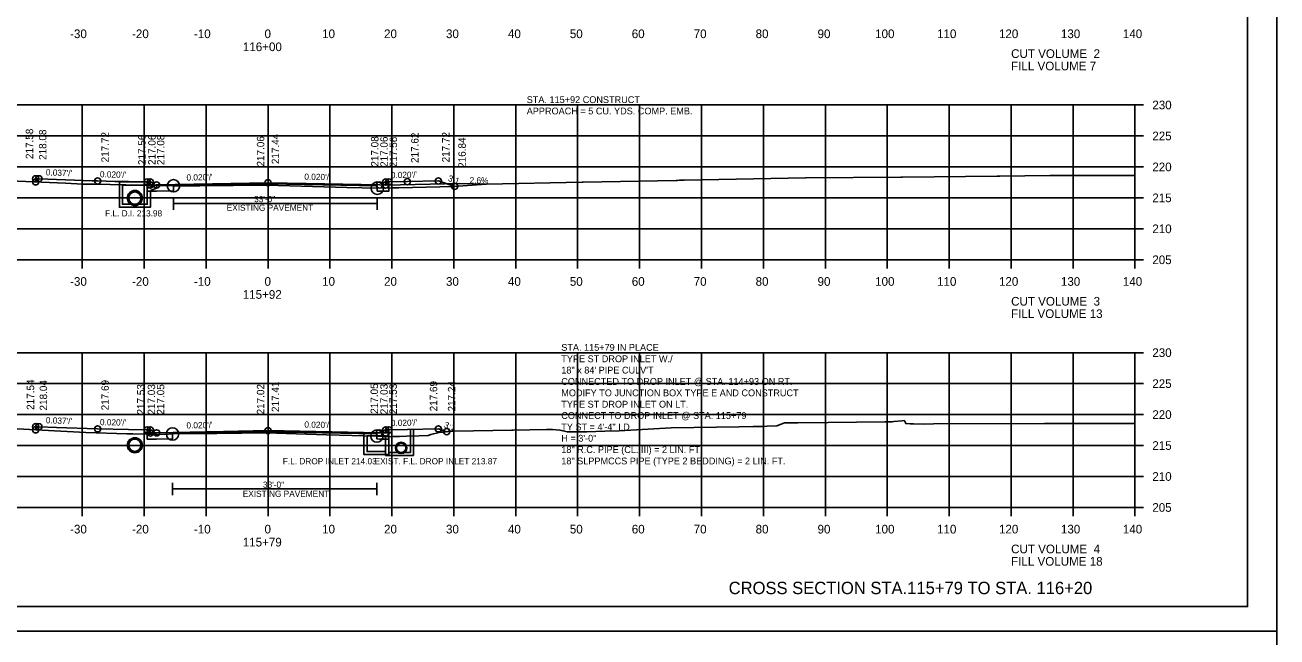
# Model space of a CAD drawing. Extents: x 1368968 to 1369915, y 377395 to 380381.
# Drawn here: x 1369712.5 to 1369914.7, y 378887.1 to 378986 of the extents above; entities that cross this region are included whole.
import ezdxf

# ---------------------------------------------------------------- set-up
doc = ezdxf.new("R2010")
doc.units = 0
for name, color, linetype in [('Default', 7, 'Continuous'), ('S_BORDER_NO_PLOT', 7, 'Continuous'), ('S_BREAKLINE_ANNOT', 7, 'Continuous'), ('S_BRIDGE', 7, 'Continuous'), ('S_BRIDGE_ANNOT', 7, 'Continuous'), ('S_CONTOUR_MINOR', 7, 'Continuous'), ('S_CROSS_DRAIN', 7, 'Continuous'), ('S_CTL_TABLE', 7, 'Continuous'), ('S_CURB_ANNOT', 7, 'Continuous'), ('S_DITCHLINE_ANNOT', 7, 'Continuous'), ('S_DROP_INLET', 7, 'Continuous'), ('S_EXIST_ROW_ANNOT', 7, 'Continuous'), ('S_EXISTING_ALIGNMENT_ANNOT', 7, 'Continuous'), ('S_FENCE', 7, 'Continuous')]:
    doc.layers.add(name, color=color, linetype=linetype)

msp = doc.modelspace()

# ---------------------------------------------------------------- linework, layer by layer
at = {"layer": 'Default'}
for p, q in [((1369736.52, 378960.01), (1369736.52, 378959.18)), ((1369774.78, 378919.56), (1369774.78, 378920.64)), ((1369775.28, 378919.58), (1369775.28, 378920.65)), ((1369736.37, 378919.97), (1369736.37, 378919.14)), ((1369770.78, 378916.41), (1369770.78, 378919.47)), ((1369771.28, 378916.91), (1369771.28, 378919.48)), ((1369774.78, 378916.91), (1369774.78, 378919.56)), ((1369775.28, 378916.41), (1369775.28, 378919.58)), ((1369771.28, 378916.91), (1369774.78, 378916.91)), ((1369770.78, 378916.41), (1369775.28, 378916.41))]:
    msp.add_line(p, q, dxfattribs=at)
at = {"layer": 'S_BORDER_NO_PLOT'}
for points in [[(1369732.27, 378960.61), (1369732.28, 378959.1), (1369733.78, 378959.13), (1369736.52, 378959.18), (1369736.52, 378960.01), (1369751.78, 378960.32), (1369769.43, 378959.96), (1369769.43, 378959.13), (1369769.78, 378959.13), (1369771.28, 378959.1), (1369771.29, 378960.61)], [(1369732.27, 378920.57), (1369732.28, 378919.06), (1369733.78, 378919.09), (1369736.37, 378919.14), (1369736.37, 378919.97), (1369751.78, 378920.28), (1369769.36, 378919.93), (1369769.36, 378919.1), (1369769.78, 378919.09), (1369771.28, 378919.06), (1369771.29, 378920.57)]]:
    msp.add_lwpolyline(points, dxfattribs=at)
at = {"layer": 'S_BREAKLINE_ANNOT'}
for p, q in [((1369891.78, 378948.04), (1369891.78, 378973.04)), ((1369893.18, 378973.04), (1369891.78, 378973.04)), ((1369893.18, 378968.04), (1369891.78, 378968.04)), ((1369893.18, 378963.04), (1369891.78, 378963.04)), ((1369893.18, 378958.04), (1369891.78, 378958.04)), ((1369893.18, 378953.04), (1369891.78, 378953.04)), ((1369611.78, 378948.04), (1369891.78, 378948.04)), ((1369721.78, 378946.64), (1369721.78, 378948.04)), ((1369731.78, 378946.64), (1369731.78, 378948.04)), ((1369741.78, 378946.64), (1369741.78, 378948.04)), ((1369751.78, 378946.64), (1369751.78, 378948.04)), ((1369761.78, 378946.64), (1369761.78, 378948.04)), ((1369771.78, 378946.64), (1369771.78, 378948.04)), ((1369781.78, 378946.64), (1369781.78, 378948.04)), ((1369791.78, 378946.64), (1369791.78, 378948.04)), ((1369801.78, 378946.64), (1369801.78, 378948.04)), ((1369811.78, 378946.64), (1369811.78, 378948.04)), ((1369821.78, 378946.64), (1369821.78, 378948.04)), ((1369831.78, 378946.64), (1369831.78, 378948.04)), ((1369841.78, 378946.64), (1369841.78, 378948.04)), ((1369851.78, 378946.64), (1369851.78, 378948.04)), ((1369861.78, 378946.64), (1369861.78, 378948.04)), ((1369871.78, 378946.64), (1369871.78, 378948.04)), ((1369881.78, 378946.64), (1369881.78, 378948.04)), ((1369891.78, 378946.64), (1369891.78, 378948.04)), ((1369893.18, 378948.04), (1369891.78, 378948.04)), ((1369891.78, 378908.04), (1369891.78, 378933.04)), ((1369893.18, 378933.04), (1369891.78, 378933.04)), ((1369893.18, 378928.04), (1369891.78, 378928.04)), ((1369893.18, 378923.04), (1369891.78, 378923.04)), ((1369893.18, 378918.04), (1369891.78, 378918.04)), ((1369893.18, 378913.04), (1369891.78, 378913.04)), ((1369611.78, 378908.04), (1369891.78, 378908.04)), ((1369721.78, 378906.64), (1369721.78, 378908.04)), ((1369731.78, 378906.64), (1369731.78, 378908.04)), ((1369741.78, 378906.64), (1369741.78, 378908.04)), ((1369751.78, 378906.64), (1369751.78, 378908.04)), ((1369761.78, 378906.64), (1369761.78, 378908.04)), ((1369771.78, 378906.64), (1369771.78, 378908.04)), ((1369781.78, 378906.64), (1369781.78, 378908.04)), ((1369791.78, 378906.64), (1369791.78, 378908.04)), ((1369801.78, 378906.64), (1369801.78, 378908.04)), ((1369811.78, 378906.64), (1369811.78, 378908.04)), ((1369821.78, 378906.64), (1369821.78, 378908.04)), ((1369831.78, 378906.64), (1369831.78, 378908.04)), ((1369841.78, 378906.64), (1369841.78, 378908.04)), ((1369851.78, 378906.64), (1369851.78, 378908.04)), ((1369861.78, 378906.64), (1369861.78, 378908.04)), ((1369871.78, 378906.64), (1369871.78, 378908.04)), ((1369881.78, 378906.64), (1369881.78, 378908.04)), ((1369891.78, 378906.64), (1369891.78, 378908.04)), ((1369893.18, 378908.04), (1369891.78, 378908.04))]:
    msp.add_line(p, q, dxfattribs=at)
at = {"layer": 'S_BRIDGE_ANNOT'}
for q in [(1369909.96, 379097.5), (1369593.78, 378892.04)]:
    msp.add_line((1369909.96, 378892.04), q, dxfattribs=at)
at = {"layer": 'S_CROSS_DRAIN'}
for p, q in [((1369770.78, 378960.11), (1369782.77, 378960.35)), ((1369786.84, 378960.24), (1369782.77, 378960.35)), ((1369736.52, 378957.12), (1369762.84, 378957.12)), ((1369736.52, 378957.12), (1369769.43, 378957.12)), ((1369736.37, 378911.04), (1369769.36, 378911.04))]:
    msp.add_line(p, q, dxfattribs=at)
at = {"layer": 'S_CTL_TABLE'}
for points in [[(1369710.09, 378960.81), (1369719.09, 378960.4), (1369721.88, 378960.28), (1369723, 378960.26), (1369723.69, 378960.25), (1369736.52, 378959.99), (1369740.76, 378960.01), (1369751.61, 378960.1), (1369764.52, 378959.74), (1369769.43, 378959.61), (1369771.81, 378959.66), (1369772.89, 378959.68), (1369781.71, 378959.87), (1369787.03, 378960.25), (1369787.04, 378960.25), (1369787.05, 378960.25), (1369802.53, 378960.56), (1369802.58, 378960.56), (1369802.63, 378960.56), (1369802.67, 378960.56), (1369817.71, 378960.86), (1369817.82, 378960.86), (1369817.91, 378960.87), (1369818.24, 378960.88), (1369818.66, 378960.89), (1369818.75, 378960.89), (1369818.86, 378960.9), (1369818.99, 378960.9), (1369838.55, 378961.25), (1369838.56, 378961.25), (1369838.65, 378961.25), (1369853.99, 378961.38), (1369854.16, 378961.38), (1369854.17, 378961.38), (1369854.22, 378961.39), (1369854.23, 378961.38), (1369869.55, 378961.52), (1369869.59, 378961.52), (1369869.62, 378961.52), (1369869.97, 378961.52), (1369878.03, 378961.64), (1369885.57, 378961.65), (1369891.78, 378961.64)], [(1369711.26, 378920.74), (1369722.37, 378920.16), (1369728.98, 378919.95), (1369729.96, 378919.94), (1369735.12, 378919.83), (1369736.37, 378919.91), (1369743.49, 378919.97), (1369751.53, 378920.07), (1369761.25, 378919.79), (1369769.36, 378919.57), (1369770.52, 378919.5), (1369770.79, 378919.47), (1369771.94, 378919.49), (1369773.02, 378919.51), (1369774.16, 378919.55), (1369776.18, 378919.6), (1369777.63, 378919.66), (1369778.07, 378919.81), (1369778.49, 378919.94), (1369778.97, 378920.04), (1369779.63, 378920.18), (1369780, 378920.22), (1369781.25, 378920.34), (1369781.85, 378920.37), (1369781.89, 378920.37), (1369791.14, 378920.53), (1369791.35, 378920.53), (1369796.75, 378920.64), (1369797.01, 378920.65), (1369797.73, 378920.65), (1369798.91, 378920.54), (1369800.12, 378920.24), (1369800.98, 378920.25), (1369803.05, 378920.24), (1369803.19, 378920.25), (1369803.28, 378920.25), (1369806.18, 378920.34), (1369808.51, 378920.43), (1369816.89, 378920.88), (1369827.86, 378921.04), (1369830.12, 378921.1), (1369831.65, 378921.13), (1369832.38, 378921.16), (1369833.87, 378921.22), (1369833.92, 378921.22), (1369833.96, 378921.22), (1369834.65, 378921.47), (1369835.19, 378921.7), (1369835.48, 378921.71), (1369837.02, 378921.72), (1369837.32, 378921.73), (1369842.23, 378921.77), (1369851.39, 378921.85), (1369852.01, 378921.86), (1369852.48, 378921.88), (1369852.59, 378921.89), (1369852.85, 378921.91), (1369854.21, 378922.05), (1369854.5, 378922.09), (1369854.6, 378921.97), (1369854.77, 378921.58), (1369855.47, 378921.54), (1369856.03, 378921.54), (1369857.83, 378921.52), (1369859.26, 378921.54), (1369877.18, 378921.58), (1369877.94, 378921.59), (1369882.37, 378921.6), (1369891.78, 378921.62)]]:
    msp.add_lwpolyline(points, dxfattribs=at)
at = {"layer": 'S_CURB_ANNOT'}
for points in [[(1369714.27, 378960.62), (1369714.27, 378961.12), (1369714.77, 378961.12), (1369723.38, 378960.8), (1369724.27, 378960.77), (1369727.03, 378960.71), (1369729.27, 378960.67), (1369732.27, 378960.61), (1369732.34, 378960.61), (1369732.77, 378960.61), (1369732.78, 378960.11), (1369733.78, 378960.13), (1369733.78, 378960.13), (1369751.78, 378960.49), (1369757.93, 378960.36), (1369769.78, 378960.13), (1369770.78, 378960.11), (1369770.79, 378960.61), (1369771.06, 378960.61), (1369771.29, 378960.61), (1369774.29, 378960.67), (1369779.29, 378960.77), (1369781.92, 378959.89)], [(1369714.27, 378920.58), (1369714.27, 378921.08), (1369714.77, 378921.08), (1369717.63, 378920.98), (1369724.27, 378920.73), (1369729.27, 378920.63), (1369732.27, 378920.57), (1369732.43, 378920.57), (1369732.77, 378920.57), (1369732.78, 378920.07), (1369733.78, 378920.09), (1369744.57, 378920.31), (1369751.78, 378920.45), (1369769.78, 378920.09), (1369770.78, 378920.07), (1369770.78, 378920.4), (1369770.79, 378920.57), (1369770.82, 378920.57), (1369771.29, 378920.57), (1369774.29, 378920.63), (1369779.29, 378920.73), (1369780.64, 378920.28)]]:
    msp.add_lwpolyline(points, dxfattribs=at)
at = {"layer": 'S_DITCHLINE_ANNOT'}
for p, q in [((1369611.78, 378973.04), (1369891.78, 378973.04)), ((1369721.78, 378948.04), (1369721.78, 378973.04)), ((1369731.78, 378948.04), (1369731.78, 378973.04)), ((1369741.78, 378948.04), (1369741.78, 378973.04)), ((1369751.78, 378948.04), (1369751.78, 378973.04)), ((1369761.78, 378948.04), (1369761.78, 378973.04)), ((1369771.78, 378948.04), (1369771.78, 378973.04)), ((1369781.78, 378948.04), (1369781.78, 378973.04)), ((1369791.78, 378948.04), (1369791.78, 378973.04)), ((1369801.78, 378948.04), (1369801.78, 378973.04)), ((1369811.78, 378948.04), (1369811.78, 378973.04)), ((1369821.78, 378948.04), (1369821.78, 378973.04)), ((1369831.78, 378948.04), (1369831.78, 378973.04)), ((1369841.78, 378948.04), (1369841.78, 378973.04)), ((1369851.78, 378948.04), (1369851.78, 378973.04)), ((1369861.78, 378948.04), (1369861.78, 378973.04)), ((1369871.78, 378948.04), (1369871.78, 378973.04)), ((1369881.78, 378948.04), (1369881.78, 378973.04)), ((1369891.78, 378948.04), (1369891.78, 378973.04)), ((1369611.78, 378968.04), (1369891.78, 378968.04)), ((1369611.78, 378963.04), (1369891.78, 378963.04)), ((1369611.78, 378958.04), (1369891.78, 378958.04)), ((1369611.78, 378953.04), (1369891.78, 378953.04)), ((1369611.78, 378948.04), (1369891.78, 378948.04)), ((1369611.78, 378933.04), (1369891.78, 378933.04)), ((1369721.78, 378908.04), (1369721.78, 378933.04)), ((1369731.78, 378908.04), (1369731.78, 378933.04)), ((1369741.78, 378908.04), (1369741.78, 378933.04)), ((1369751.78, 378908.04), (1369751.78, 378933.04)), ((1369761.78, 378908.04), (1369761.78, 378933.04)), ((1369771.78, 378908.04), (1369771.78, 378933.04)), ((1369781.78, 378908.04), (1369781.78, 378933.04)), ((1369791.78, 378908.04), (1369791.78, 378933.04)), ((1369801.78, 378908.04), (1369801.78, 378933.04)), ((1369811.78, 378908.04), (1369811.78, 378933.04)), ((1369821.78, 378908.04), (1369821.78, 378933.04)), ((1369831.78, 378908.04), (1369831.78, 378933.04)), ((1369841.78, 378908.04), (1369841.78, 378933.04)), ((1369851.78, 378908.04), (1369851.78, 378933.04)), ((1369861.78, 378908.04), (1369861.78, 378933.04)), ((1369871.78, 378908.04), (1369871.78, 378933.04)), ((1369881.78, 378908.04), (1369881.78, 378933.04)), ((1369891.78, 378908.04), (1369891.78, 378933.04)), ((1369611.78, 378928.04), (1369891.78, 378928.04)), ((1369611.78, 378923.04), (1369891.78, 378923.04)), ((1369611.78, 378918.04), (1369891.78, 378918.04)), ((1369611.78, 378913.04), (1369891.78, 378913.04)), ((1369611.78, 378908.04), (1369891.78, 378908.04))]:
    msp.add_line(p, q, dxfattribs=at)
at = {"layer": 'S_DROP_INLET'}
for p, q in [((1369730.28, 378958.66), (1369730.28, 378958.66)), ((1369730.28, 378956.83), (1369730.28, 378956.82)), ((1369581.38, 378888.06), (1369914.71, 378888.06)), ((1369581.38, 378888.06), (1369914.71, 378888.06))]:
    msp.add_line(p, q, dxfattribs=at)
for points in [[(1369581.37, 379101.4), (1369914.71, 379101.4), (1369914.71, 378888.06), (1369581.37, 378888.06)], [(1369827.7, 379097.5), (1369827.7, 379087.62), (1369863.43, 379087.62), (1369863.43, 379084.7), (1369886.63, 379084.7), (1369886.63, 379060.37), (1369909.96, 379060.37), (1369909.96, 378892.04), (1369593.78, 378892.04), (1369593.78, 379097.5)], [(1369581.37, 378888.06), (1369914.71, 378888.06), (1369914.71, 378674.72), (1369581.37, 378674.72)]]:
    msp.add_lwpolyline(points, close=True, dxfattribs=at)
for centre, radius in [((1369714.27, 378961.12), 0.5), ((1369714.27, 378960.62), 0.5), ((1369714.77, 378961.12), 0.5), ((1369724.27, 378960.77), 0.5), ((1369732.27, 378960.61), 0.5), ((1369732.77, 378960.61), 0.5), ((1369770.79, 378960.61), 0.5), ((1369771.29, 378960.61), 0.5), ((1369774.29, 378960.67), 0.5), ((1369779.29, 378960.77), 0.5), ((1369730.28, 378958.02), 1.21), ((1369730.28, 378958.01), 1.21), ((1369732.78, 378960.11), 0.5), ((1369733.78, 378960.13), 0.5), ((1369733.78, 378960.13), 0.5), ((1369736.52, 378959.99), 1), ((1369751.78, 378960.49), 0.5), ((1369769.43, 378959.61), 1), ((1369769.78, 378960.13), 0.5), ((1369769.78, 378960.13), 0.5), ((1369770.78, 378960.11), 0.5), ((1369781.92, 378959.89), 0.5), ((1369714.27, 378921.08), 0.5), ((1369714.27, 378920.58), 0.5), ((1369714.77, 378921.08), 0.5), ((1369724.27, 378920.73), 0.5), ((1369732.27, 378920.57), 0.5), ((1369732.77, 378920.57), 0.5), ((1369732.78, 378920.07), 0.5), ((1369733.78, 378920.09), 0.5), ((1369733.78, 378920.09), 0.5), ((1369736.37, 378919.91), 1), ((1369751.78, 378920.45), 0.5), ((1369769.36, 378919.57), 1), ((1369769.78, 378920.09), 0.5), ((1369769.78, 378920.09), 0.5), ((1369770.78, 378920.07), 0.5), ((1369770.79, 378920.57), 0.5), ((1369771.29, 378920.57), 0.5), ((1369779.29, 378920.73), 0.5), ((1369780.64, 378920.28), 0.5), ((1369730.28, 378918.09), 1.21), ((1369730.28, 378918.08), 1.21), ((1369773.28, 378917.66), 0.917)]:
    msp.add_circle(centre, radius, dxfattribs=at)
at = {"layer": 'S_EXIST_ROW_ANNOT'}
for p, q in [((1369727.78, 378960.61), (1369732.53, 378960.61)), ((1369727.78, 378959.11), (1369727.78, 378960.61)), ((1369728.28, 378959.11), (1369728.28, 378960.11)), ((1369728.28, 378960.11), (1369732.28, 378960.11)), ((1369732.61, 378960.44), (1369732.28, 378960.11)), ((1369733.78, 378960.13), (1369732.28, 378959.61)), ((1369732.28, 378959.11), (1369732.28, 378959.61)), ((1369732.61, 378960.44), (1369732.53, 378960.61)), ((1369733.78, 378959.6), (1369732.78, 378959.25)), ((1369732.78, 378959.11), (1369732.78, 378959.25)), ((1369730.28, 378958.5), (1369730.28, 378958.49)), ((1369730.28, 378957), (1369730.28, 378956.99)), ((1369736.52, 378956.12), (1369736.52, 378958.12)), ((1369736.52, 378956.12), (1369736.52, 378958.12)), ((1369769.43, 378956.12), (1369769.43, 378958.12)), ((1369736.37, 378910.04), (1369736.37, 378912.04)), ((1369769.36, 378910.04), (1369769.36, 378912.04))]:
    msp.add_line(p, q, dxfattribs=at)
for points in [[(1369732.78, 378959.11), (1369732.78, 378956.52), (1369730.28, 378956.52), (1369727.78, 378956.52), (1369727.78, 378959.11)], [(1369732.28, 378959.11), (1369732.28, 378957.02), (1369730.28, 378957.02), (1369728.28, 378957.02), (1369728.28, 378959.11)], [(1369733.78, 378959.6), (1369733.78, 378960.13)]]:
    msp.add_lwpolyline(points, dxfattribs=at)
for points in [[(1369769.28, 378920.09), (1369771.28, 378920.09), (1369771.28, 378916.57), (1369769.28, 378916.57), (1369767.28, 378916.57), (1369767.28, 378920.09)], [(1369769.28, 378919.59), (1369770.78, 378919.59), (1369770.78, 378917.07), (1369769.28, 378917.07), (1369767.78, 378917.07), (1369767.78, 378919.59)]]:
    msp.add_lwpolyline(points, close=True, dxfattribs=at)
for centre, radius in [((1369730.28, 378958.02), 1), ((1369730.28, 378958.01), 1), ((1369730.28, 378918.09), 1), ((1369730.28, 378918.08), 1), ((1369773.28, 378917.66), 0.75)]:
    msp.add_circle(centre, radius, dxfattribs=at)
at = {"layer": 'S_EXISTING_ALIGNMENT_ANNOT'}
for p, q in [((1369751.78, 378960.1), (1369751.78, 378970.1)), ((1369751.78, 378920.07), (1369751.78, 378930.07))]:
    msp.add_line(p, q, dxfattribs=at)

# ---------------------------------------------------------------- texts
at = {"layer": 'S_BRIDGE'}
for s, p in [('-30', (1369719.82, 378983.84)), ('-20', (1369729.82, 378983.84)), ('-10', (1369739.82, 378983.84)), ('0', (1369751.22, 378983.84)), ('10', (1369760.52, 378983.84)), ('20', (1369770.52, 378983.84)), ('30', (1369780.52, 378983.84)), ('40', (1369790.52, 378983.84)), ('50', (1369800.52, 378983.84)), ('60', (1369810.52, 378983.84)), ('70', (1369820.52, 378983.84)), ('80', (1369830.52, 378983.84)), ('90', (1369840.52, 378983.84)), ('100', (1369849.82, 378983.84)), ('110', (1369859.82, 378983.84)), ('120', (1369869.82, 378983.84)), ('130', (1369879.82, 378983.84)), ('140', (1369889.82, 378983.84)), ('116+00', (1369747.72, 378981.74)), ('CUT VOLUME  2', (1369871.78, 378980.64)), ('FILL VOLUME 7', (1369871.78, 378978.64)), ('230', (1369894.58, 378972.34)), ('225', (1369894.58, 378967.34)), ('220', (1369894.58, 378962.34)), ('215', (1369894.58, 378957.34)), ('210', (1369894.58, 378952.34)), ('205', (1369894.58, 378947.34)), ('-30', (1369719.82, 378943.84)), ('-20', (1369729.82, 378943.84)), ('-10', (1369739.82, 378943.84)), ('0', (1369751.22, 378943.84)), ('10', (1369760.52, 378943.84)), ('20', (1369770.52, 378943.84)), ('30', (1369780.52, 378943.84)), ('40', (1369790.52, 378943.84)), ('50', (1369800.52, 378943.84)), ('60', (1369810.52, 378943.84)), ('70', (1369820.52, 378943.84)), ('80', (1369830.52, 378943.84)), ('90', (1369840.52, 378943.84)), ('100', (1369849.82, 378943.84)), ('110', (1369859.82, 378943.84)), ('120', (1369869.82, 378943.84)), ('130', (1369879.82, 378943.84)), ('140', (1369889.82, 378943.84)), ('115+92', (1369747.7, 378941.74)), ('CUT VOLUME  3', (1369871.78, 378940.64)), ('FILL VOLUME 13', (1369871.78, 378938.64)), ('230', (1369894.58, 378932.34)), ('225', (1369894.58, 378927.34)), ('220', (1369894.58, 378922.34)), ('215', (1369894.58, 378917.34)), ('210', (1369894.58, 378912.34)), ('205', (1369894.58, 378907.34)), ('-30', (1369719.82, 378903.84)), ('-20', (1369729.82, 378903.84)), ('-10', (1369739.82, 378903.84)), ('0', (1369751.22, 378903.84)), ('10', (1369760.52, 378903.84)), ('20', (1369770.52, 378903.84)), ('30', (1369780.52, 378903.84)), ('40', (1369790.52, 378903.84)), ('50', (1369800.52, 378903.84)), ('60', (1369810.52, 378903.84)), ('70', (1369820.52, 378903.84)), ('80', (1369830.52, 378903.84)), ('90', (1369840.52, 378903.84)), ('100', (1369849.82, 378903.84)), ('110', (1369859.82, 378903.84)), ('120', (1369869.82, 378903.84)), ('130', (1369879.82, 378903.84)), ('140', (1369889.82, 378903.84)), ('115+79', (1369747.7, 378901.74)), ('CUT VOLUME  4', (1369871.78, 378900.64)), ('FILL VOLUME 18', (1369871.78, 378898.64))]:
    msp.add_text(s, height=1.4, dxfattribs=at).set_placement(p)
at = {"layer": 'S_CONTOUR_MINOR'}
for s, height, p in [('STA. 115+92 CONSTRUCT ', 1.1, (1369793.56, 378973.35)), ('APPROACH = 5 CU. YDS. COMP. EMB.', 1.1, (1369793.56, 378971.52)), ('STA. 115+79 IN PLACE', 1.1, (1369799.14, 378933.34)), ('TYPE ST DROP INLET W./ ', 1.1, (1369799.14, 378931.5)), ('18" x 84\' PIPE CULV\'T ', 1.1, (1369799.14, 378929.67)), ('CONNECTED TO DROP INLET @ STA. 114+93 ON RT. ', 1.1, (1369799.14, 378927.84)), ('MODIFY TO JUNCTION BOX TYPE E AND CONSTRUCT ', 1.1, (1369799.14, 378926)), ('TYPE ST DROP INLET ON LT.', 1.1, (1369799.14, 378924.17)), ('CONNECT TO DROP INLET @ STA. 115+79', 1.1, (1369799.14, 378922.34)), ('TY ST = 4\'-4" I.D.', 1.1, (1369799.14, 378920.5)), ('H = 3\'-0"', 1.1, (1369799.14, 378918.67)), ('18" R.C. PIPE (CL. III) = 2 LIN. FT.', 1.1, (1369799.14, 378916.84)), ('18" SLPPMCCS PIPE (TYPE 2 BEDDING) = 2 LIN. FT.', 1.1, (1369799.14, 378915)), ('CROSS SECTION STA.115+79 TO STA. 116+20', 2, (1369826.17, 378894.04))]:
    msp.add_text(s, height=height, dxfattribs=at).set_placement(p)
at = {"layer": 'S_CROSS_DRAIN'}
msp.add_text('2.6%', height=1, rotation=358.5106, dxfattribs=at).set_placement((1369784.32, 378960.4))
at = {"layer": 'S_EXIST_ROW_ANNOT'}
for s, p in [('EXISTING PAVEMENT', (1369745.11, 378955.95)), ('33\'-0"', (1369749.54, 378957.35)), ('F.L. D.I. 213.98', (1369725.47, 378955.04)), ('F.L. DROP INLET 214.03', (1369754.17, 378915.01)), ('EXIST. F.L. DROP INLET 213.87', (1369768.99, 378915.01)), ('EXISTING PAVEMENT', (1369747.7, 378909.75)), ('33\'-0"', (1369750.97, 378911.22))]:
    msp.add_text(s, height=1, dxfattribs=at).set_placement(p)
at = {"layer": 'S_EXISTING_ALIGNMENT_ANNOT'}
for s, p in [('217.58', (1369713.86, 378964.31)), ('218.08', (1369715.99, 378964.17)), ('217.72', (1369726.07, 378963.77)), ('217.56', (1369732.02, 378963.34)), ('217.06', (1369733.63, 378963.35)), ('217.08', (1369735.05, 378963.34)), ('217.06', (1369751.18, 378963.1)), ('217.44', (1369753.58, 378963.49)), ('217.08', (1369769.62, 378963.08)), ('217.06', (1369771.11, 378963.04)), ('217.56', (1369772.62, 378963)), ('217.62', (1369776.09, 378963.67)), ('217.72', (1369781.09, 378963.77)), ('216.84', (1369783.72, 378962.89)), ('217.54', (1369714.02, 378923.8)), ('218.04', (1369716.11, 378923.7)), ('217.69', (1369726.07, 378923.73)), ('217.53', (1369731.83, 378923.05)), ('217.03', (1369733.55, 378923.04)), ('217.05', (1369735.03, 378923.03)), ('217.02', (1369751.18, 378923.07)), ('217.41', (1369753.58, 378923.45)), ('217.05', (1369769.54, 378923.17)), ('217.03', (1369771.11, 378923.09)), ('217.53', (1369772.59, 378923.11)), ('217.69', (1369779.11, 378923.56)), ('217.24', (1369782.03, 378923.54))]:
    msp.add_text(s, height=1.2, rotation=90, dxfattribs=at).set_placement(p)
at = {"layer": 'S_FENCE'}
for s, rotation, p in [("0.037'/'", 357.8719, (1369715.89, 378961.68)), ("0.020'/'", 358.8543, (1369724.63, 378961.36)), ("0.020'/'", 1.1458, (1369738.62, 378960.82)), ("0.020'/'", 358.8542, (1369757.64, 378960.97)), ("0.020'/'", 1.1457, (1369771.62, 378961.21)), ('3:1', 341.5596, (1369780.76, 378960.8)), ("0.037'/'", 357.902, (1369715.89, 378921.64)), ("0.020'/'", 358.8543, (1369724.63, 378921.33)), ("0.020'/'", 1.1457, (1369738.62, 378920.79)), ("0.020'/'", 358.8542, (1369757.64, 378920.94)), ("0.020'/'", 1.1458, (1369771.63, 378921.18)), ('3:1', 341.5534, (1369780.12, 378920.98))]:
    msp.add_text(s, height=1, rotation=rotation, dxfattribs=at).set_placement(p)

doc.saveas('drawing.dxf')
